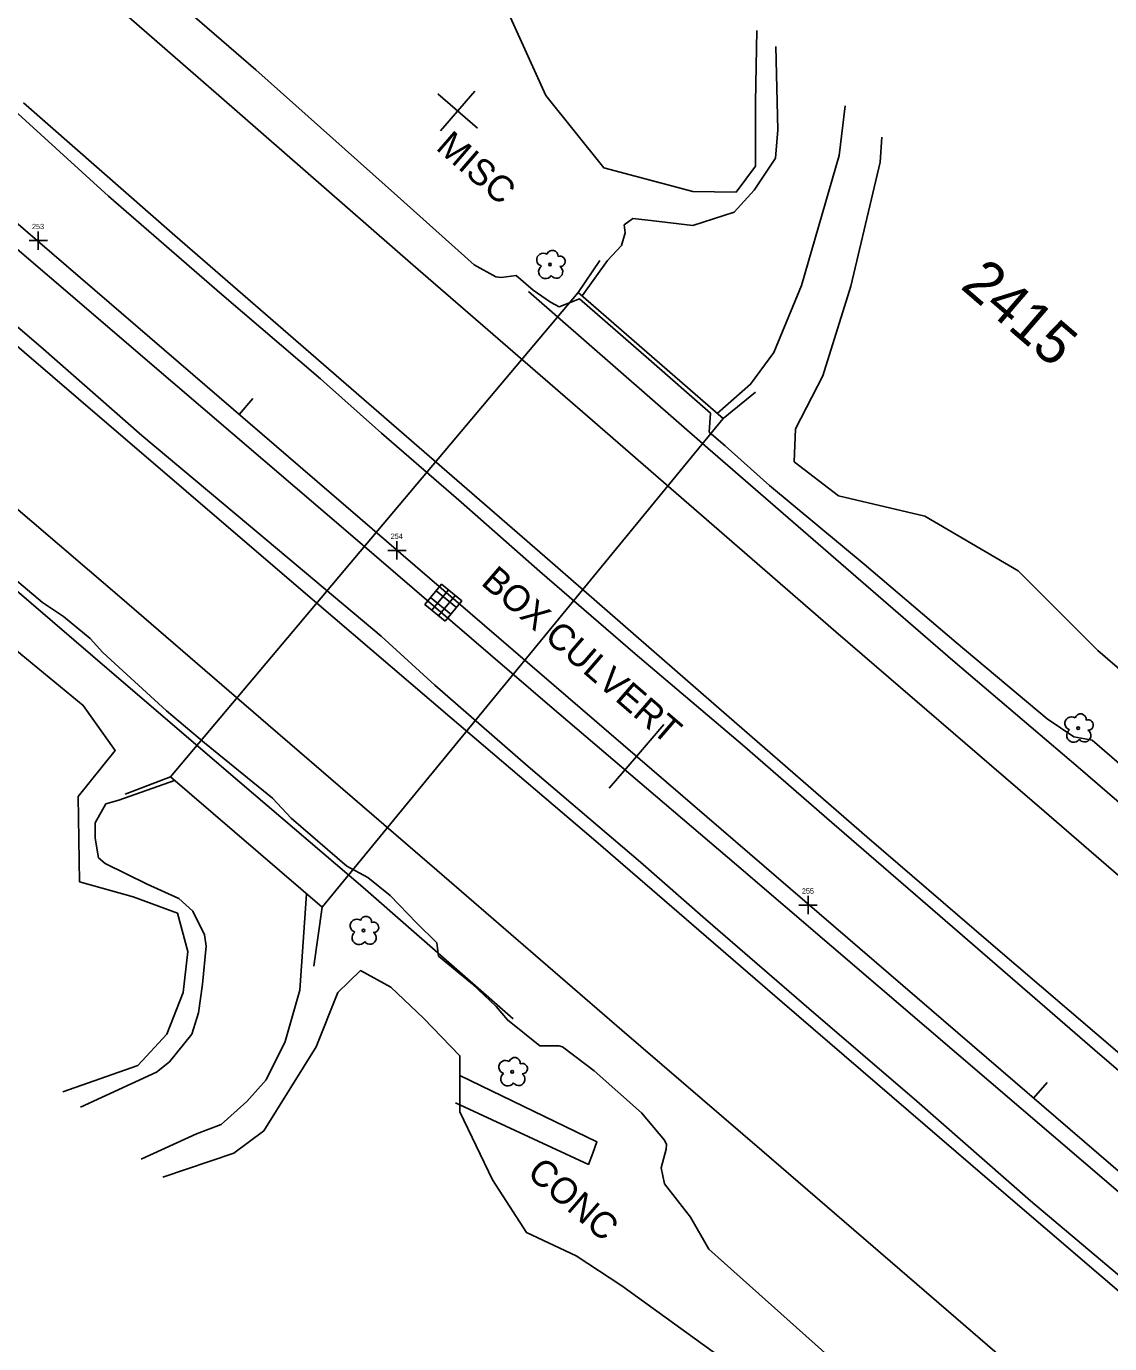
# Model space of a CAD drawing. Extents: x 2076109 to 2080761, y 592812 to 596750.
# Drawn here: x 2079627.6 to 2079834.4, y 593575.6 to 593826.9 of the extents above; entities that cross this region are included whole.
import ezdxf

# ---------------------------------------------------------------- set-up
doc = ezdxf.new("R2010")
doc.units = 0
for name, color, linetype in [('Default', 7, 'Continuous'), ('RD_EX_Bridge', 7, 'Continuous'), ('RD_EX_Bridge_txCode', 7, 'Continuous'), ('RD_EX_Conc', 7, 'Continuous'), ('RD_EX_Conc_txCode', 7, 'Continuous'), ('RD_EX_DR_Inlet', 7, 'Continuous'), ('RD_EX_DR_Pipe', 7, 'Continuous'), ('RD_EX_GuardRail', 7, 'Continuous'), ('RD_EX_H2O', 7, 'Continuous'), ('RD_EX_Misc', 7, 'Continuous'), ('RD_EX_Misc_txCode', 7, 'Continuous'), ('RD_EX_Road', 7, 'Continuous'), ('RD_EX_VEG', 7, 'Continuous'), ('RD_HC_Cl', 7, 'Continuous'), ('RD_HC_Data_Tic', 7, 'Continuous'), ('RD_HC_TX_Sta50', 7, 'Continuous')]:
    doc.layers.add(name, color=color, linetype=linetype)

msp = doc.modelspace()

# ---------------------------------------------------------------- linework, layer by layer
at = {"layer": 'Default'}
for p, q in [((2079631.63, 593786.02), (2079628.13, 593786.02)), ((2079631.63, 593786.02), (2079628.13, 593786.02)), ((2079629.88, 593787.77), (2079629.88, 593784.27)), ((2079629.88, 593787.77), (2079629.88, 593784.27)), ((2079698.34, 593728.68), (2079698.34, 593725.18)), ((2079698.34, 593728.68), (2079698.34, 593725.18)), ((2079700.09, 593726.93), (2079696.59, 593726.93)), ((2079700.09, 593726.93), (2079696.59, 593726.93)), ((2079776.81, 593661), (2079776.81, 593657.5)), ((2079776.81, 593661), (2079776.81, 593657.5)), ((2079778.56, 593659.25), (2079775.06, 593659.25)), ((2079778.56, 593659.25), (2079775.06, 593659.25))]:
    msp.add_line(p, q, dxfattribs=at)
at = {"layer": 'RD_EX_Bridge'}
for p, q in [((2079655.12, 593683.72), (2079646.47, 593680.41)), ((2079655.12, 593683.72), (2079646.47, 593680.41)), ((2079655.12, 593683.72), (2079684.06, 593658.88)), ((2079655.12, 593683.72), (2079684.06, 593658.88)), ((2079682.49, 593647.64), (2079684.06, 593658.88)), ((2079682.49, 593647.64), (2079684.06, 593658.88))]:
    msp.add_line(p, q, dxfattribs=at)
msp.add_lwpolyline([(2079737.04, 593782.21), (2079732.93, 593776.12), (2079760.58, 593752.07), (2079766.75, 593757.09)], dxfattribs=at)
msp.add_lwpolyline([(2079737.04, 593782.21), (2079732.93, 593776.12), (2079760.58, 593752.07), (2079766.75, 593757.09)], dxfattribs=at)
at = {"layer": 'RD_EX_Conc'}
msp.add_lwpolyline([(2079710.35, 593626.77), (2079736.52, 593614.13), (2079735.75, 593611.96), (2079734.89, 593609.79), (2079709.53, 593621.55)], dxfattribs=at)
msp.add_lwpolyline([(2079710.35, 593626.77), (2079736.52, 593614.13), (2079735.75, 593611.96), (2079734.89, 593609.79), (2079709.53, 593621.55)], dxfattribs=at)
at = {"layer": 'RD_EX_DR_Inlet'}
for p, q in [((2079704.75, 593717.93), (2079708.61, 593714.75)), ((2079704.75, 593717.93), (2079708.61, 593714.75)), ((2079704.98, 593715.54), (2079708.16, 593719.4)), ((2079704.98, 593715.54), (2079708.16, 593719.4)), ((2079705.83, 593719.24), (2079709.69, 593716.06)), ((2079705.83, 593719.24), (2079709.69, 593716.06)), ((2079706.29, 593714.46), (2079709.47, 593718.32)), ((2079706.29, 593714.46), (2079709.47, 593718.32))]:
    msp.add_line(p, q, dxfattribs=at)
msp.add_lwpolyline([(2079707.52, 593713.44), (2079703.67, 593716.62), (2079706.85, 593720.48), (2079710.71, 593717.3)], close=True, dxfattribs=at)
msp.add_lwpolyline([(2079707.52, 593713.44), (2079703.67, 593716.62), (2079706.85, 593720.48), (2079710.71, 593717.3)], close=True, dxfattribs=at)
at = {"layer": 'RD_EX_DR_Pipe'}
for p, q in [((2079655.12, 593683.72), (2079732.93, 593776.12)), ((2079655.12, 593683.72), (2079732.93, 593776.12)), ((2079760.58, 593752.07), (2079684.06, 593658.88)), ((2079760.58, 593752.07), (2079684.06, 593658.88))]:
    msp.add_line(p, q, dxfattribs=at)
at = {"layer": 'RD_EX_GuardRail'}
for points in [[(2080184.35, 593305.04), (2080148.2, 593335.86), (2080111.67, 593367.26), (2080075.44, 593398.3), (2080039.84, 593429.28), (2080003.46, 593460.74), (2079967.36, 593491.67), (2079919.17, 593532.83), (2079871.19, 593574.23), (2079835.53, 593605.02), (2079799.41, 593635.93), (2079763.16, 593666.95), (2079727.5, 593697.27), (2079690.37, 593729.2), (2079655.55, 593758.99), (2079608.01, 593799.67)], [(2079551.16, 593782.51), (2079573.31, 593764.15), (2079609.03, 593733.58), (2079644.36, 593703.26), (2079668.38, 593682.73), (2079691.86, 593662.7), (2079720.53, 593637.58)], [(2079551.16, 593782.51), (2079573.31, 593764.15), (2079609.03, 593733.58), (2079644.36, 593703.26), (2079668.38, 593682.73), (2079691.86, 593662.7), (2079720.53, 593637.58)], [(2079915.69, 593611.77), (2079890.2, 593632.66), (2079880.48, 593640.55), (2079865.92, 593652.95), (2079847.21, 593669.28), (2079828.34, 593685.59), (2079804.41, 593705.91), (2079785.94, 593721.98), (2079757.68, 593746.46), (2079723.46, 593776.29)], [(2079915.69, 593611.77), (2079890.2, 593632.66), (2079880.48, 593640.55), (2079865.92, 593652.95), (2079847.21, 593669.28), (2079828.34, 593685.59), (2079804.41, 593705.91), (2079785.94, 593721.98), (2079757.68, 593746.46), (2079723.46, 593776.29)]]:
    msp.add_lwpolyline(points, dxfattribs=at)
at = {"layer": 'RD_EX_H2O'}
for points in [[(2079733.67, 593775.48), (2079738.53, 593782.22), (2079741.21, 593785.08), (2079741.87, 593787.48), (2079741.71, 593789.01), (2079743.36, 593790.27), (2079746.82, 593789.88), (2079754.78, 593788.92), (2079762.7, 593791.43), (2079766.52, 593795.63), (2079770.59, 593801.74), (2079771.04, 593807.18), (2079770.62, 593823.03)], [(2079733.67, 593775.48), (2079738.53, 593782.22), (2079741.21, 593785.08), (2079741.87, 593787.48), (2079741.71, 593789.01), (2079743.36, 593790.27), (2079746.82, 593789.88), (2079754.78, 593788.92), (2079762.7, 593791.43), (2079766.52, 593795.63), (2079770.59, 593801.74), (2079771.04, 593807.18), (2079770.62, 593823.03)], [(2079783.85, 593811.74), (2079782.72, 593802.27), (2079775.53, 593777.46), (2079770.25, 593764.71), (2079765.82, 593758.62), (2079759.45, 593753.06)], [(2079783.85, 593811.74), (2079782.72, 593802.27), (2079775.53, 593777.46), (2079770.25, 593764.71), (2079765.82, 593758.62), (2079759.45, 593753.06)], [(2079637.95, 593620.74), (2079652.43, 593627.36), (2079654.92, 593629.38), (2079659.21, 593634.65), (2079660.48, 593638.73), (2079661.25, 593644.19), (2079661.96, 593651.45), (2079661.61, 593653.61), (2079659.39, 593658.11), (2079656.73, 593660.5), (2079650.67, 593663.24), (2079642.69, 593667.18), (2079641.42, 593668.28), (2079640.75, 593672.01), (2079640.78, 593674.94), (2079642.81, 593678.57), (2079645.29, 593679.29), (2079655.89, 593683.06)], [(2079637.95, 593620.74), (2079652.43, 593627.36), (2079654.92, 593629.38), (2079659.21, 593634.65), (2079660.48, 593638.73), (2079661.25, 593644.19), (2079661.96, 593651.45), (2079661.61, 593653.61), (2079659.39, 593658.11), (2079656.73, 593660.5), (2079650.67, 593663.24), (2079642.69, 593667.18), (2079641.42, 593668.28), (2079640.75, 593672.01), (2079640.78, 593674.94), (2079642.81, 593678.57), (2079645.29, 593679.29), (2079655.89, 593683.06)], [(2079681.07, 593661.44), (2079679.81, 593643.05), (2079677.04, 593633.22), (2079673.4, 593625.9), (2079669.68, 593621.8), (2079664.78, 593617.43), (2079660.09, 593615.64), (2079649.66, 593610.86), (2079649.56, 593610.83)], [(2079681.07, 593661.44), (2079679.81, 593643.05), (2079677.04, 593633.22), (2079673.4, 593625.9), (2079669.68, 593621.8), (2079664.78, 593617.43), (2079660.09, 593615.64), (2079649.66, 593610.86), (2079649.56, 593610.83)]]:
    msp.add_lwpolyline(points, dxfattribs=at)
at = {"layer": 'RD_EX_Misc'}
for p, q in [((2079706.13, 593814.01), (2079713.69, 593807.47)), ((2079706.13, 593814.01), (2079713.69, 593807.47)), ((2079706.64, 593806.96), (2079713.18, 593814.53)), ((2079706.64, 593806.96), (2079713.18, 593814.53))]:
    msp.add_line(p, q, dxfattribs=at)
for points in [[(2080217.04, 593337.18), (2080172.52, 593375.33), (2080138.87, 593404.33), (2080108.48, 593430.29), (2080078.14, 593456.52), (2080038.92, 593490.11), (2080009.05, 593515.98), (2079977.29, 593543.26), (2079946.15, 593570.28), (2079919.11, 593593.43), (2079890.41, 593617.97), (2079858.75, 593645.26), (2079821.86, 593677.15), (2079782.12, 593711.42), (2079735.64, 593751.71), (2079701.45, 593781.37), (2079664.35, 593813.72), (2079643.76, 593831.64)], [(2079627.11, 593812.28), (2079655.96, 593786.97), (2079692.98, 593754.86), (2079726.56, 593725.77), (2079758.83, 593697.63), (2079788.04, 593672.28), (2079811.24, 593652.3), (2079842, 593625.98), (2079868.07, 593603.53), (2079898.03, 593577.49), (2079923.97, 593555.11), (2079945.84, 593536.38), (2079972.92, 593513.01), (2079994.98, 593494.07), (2080016.85, 593475.02), (2080049.11, 593447.31), (2080079.81, 593420.95), (2080112.25, 593393.22), (2080144.25, 593365.64), (2080177.02, 593337.45), (2080203.16, 593314.91)], [(2080178.72, 593290.98), (2080145.52, 593319.67), (2080116.25, 593344.84), (2080082.12, 593374.03), (2080051.53, 593400.34), (2080021.2, 593426.66), (2079989.82, 593453.61), (2079954.27, 593484.21), (2079917.77, 593515.59), (2079872.88, 593554.03), (2079843.75, 593579.04), (2079811.01, 593607.11), (2079771.89, 593640.76), (2079736.28, 593671.46), (2079708.41, 593695.19), (2079678.65, 593720.6), (2079637.6, 593755.82), (2079606.82, 593782.2)], [(2079590.1, 593765.16), (2079617.13, 593742.26), (2079645.39, 593718.11), (2079673.76, 593693.67), (2079705.98, 593665.94), (2079741.28, 593635.42), (2079768.01, 593612.45), (2079794.32, 593589.74), (2079821.72, 593566.1), (2079850.25, 593541.52), (2079880.79, 593515.25), (2079909.32, 593490.67), (2079940.4, 593463.94), (2079966.11, 593441.94), (2079995.57, 593416.65), (2080039.13, 593379.08), (2080076.01, 593347.24), (2080106.97, 593320.7), (2080137.83, 593294.2), (2080162.8, 593272.51)]]:
    msp.add_lwpolyline(points, dxfattribs=at)
at = {"layer": 'RD_EX_Road'}
for points in [[(2079642.44, 593843.74), (2079671.4, 593818.61), (2079698.44, 593794.49), (2079713.05, 593781.4), (2079717.21, 593779.09), (2079718.21, 593779.01), (2079721.07, 593779.37), (2079724.35, 593776.58), (2079727.62, 593774.31), (2079729.3, 593773.41), (2079733.2, 593774.9), (2079746.42, 593763.41), (2079758.17, 593753.11), (2079757.95, 593749.51), (2079761, 593746.87), (2079769.45, 593739.29), (2079787.52, 593724.31), (2079805.07, 593709.37), (2079822.43, 593694.78), (2079827.54, 593691.38), (2079831.04, 593690.71), (2079845.61, 593678.16)], [(2079915.58, 593559.4), (2079891.77, 593580.17), (2079865.9, 593602.21), (2079832.47, 593630.76), (2079804.37, 593655.14), (2079781.34, 593675), (2079764.28, 593689.81), (2079743.82, 593707.18), (2079725.61, 593722.92), (2079710.62, 593736.11), (2079695.41, 593749.27), (2079683.78, 593759.65), (2079664.93, 593775.72), (2079643.32, 593794.49), (2079625.35, 593810.82)], [(2079603.88, 593788.4), (2079630.41, 593765.74), (2079649.64, 593748.83), (2079670, 593731.78), (2079695.31, 593710.54), (2079705.57, 593701.2), (2079723.39, 593685.71), (2079744.81, 593667.42), (2079757.22, 593656.6), (2079776.93, 593639.55), (2079797.54, 593621.87), (2079819.28, 593602.83), (2079847.19, 593579.3), (2079876.99, 593553.77)], [(2079810.39, 593546.7), (2079757.88, 593593.63), (2079754.34, 593599.71), (2079749.43, 593606.09), (2079748.79, 593609.14), (2079749.7, 593612.71), (2079749.78, 593613.61), (2079749.42, 593614.43), (2079744.99, 593619.65), (2079735.99, 593627.66), (2079729.93, 593632.21), (2079729.24, 593632.44), (2079725.59, 593632.4), (2079719.42, 593637.36), (2079717.3, 593639.89), (2079712.71, 593644.23), (2079706.29, 593649.55), (2079705.96, 593652.06), (2079702.06, 593655.9), (2079697.06, 593661.1), (2079692.81, 593664.54), (2079688.8, 593666.71), (2079678.15, 593675.87), (2079674.6, 593679.68), (2079661.62, 593690.22), (2079654.37, 593696.3), (2079642.19, 593707.43), (2079639.81, 593710.09), (2079634.69, 593714.29), (2079630.72, 593716.98), (2079618.37, 593727.34)]]:
    msp.add_lwpolyline(points, dxfattribs=at)
at = {"layer": 'RD_EX_VEG'}
for points in [[(2079767.02, 593826.09), (2079766.8, 593812.46), (2079766.79, 593800.24), (2079763.08, 593795.3), (2079754.82, 593795.4), (2079737.81, 593799.93), (2079726.77, 593813.73), (2079719.92, 593828.73), (2079693.15, 593840.4), (2079683.55, 593839.8), (2079654.76, 593860.06)], [(2079767.02, 593826.09), (2079766.8, 593812.46), (2079766.79, 593800.24), (2079763.08, 593795.3), (2079754.82, 593795.4), (2079737.81, 593799.93), (2079726.77, 593813.73), (2079719.92, 593828.73), (2079693.15, 593840.4), (2079683.55, 593839.8), (2079654.76, 593860.06)], [(2079968.58, 593624.66), (2079958.38, 593631.05), (2079939.2, 593650.42), (2079923.3, 593657.31), (2079908.32, 593663.78), (2079895.34, 593672.97), (2079889.9, 593684.89), (2079877.81, 593696.83), (2079858.95, 593693.87), (2079841.76, 593699.48), (2079832.11, 593707.82), (2079816.9, 593723.01), (2079799.06, 593733.44), (2079782.58, 593737.31), (2079774.16, 593743.85), (2079774.4, 593750.13), (2079779.63, 593760.24), (2079784.95, 593777.32), (2079790.58, 593800.97), (2079790.86, 593805.75)], [(2079968.58, 593624.66), (2079958.38, 593631.05), (2079939.2, 593650.42), (2079923.3, 593657.31), (2079908.32, 593663.78), (2079895.34, 593672.97), (2079889.9, 593684.89), (2079877.81, 593696.83), (2079858.95, 593693.87), (2079841.76, 593699.48), (2079832.11, 593707.82), (2079816.9, 593723.01), (2079799.06, 593733.44), (2079782.58, 593737.31), (2079774.16, 593743.85), (2079774.4, 593750.13), (2079779.63, 593760.24), (2079784.95, 593777.32), (2079790.58, 593800.97), (2079790.86, 593805.75)], [(2079558.82, 593758.54), (2079567.11, 593752.59), (2079592, 593738.1), (2079599.15, 593721.73), (2079608.32, 593715.84), (2079616.47, 593715.83), (2079626.54, 593707.13), (2079638.47, 593697.36), (2079644.56, 593688.76), (2079637.54, 593679.97), (2079637.77, 593663.73), (2079648.02, 593660.83), (2079656.44, 593657.74), (2079658.47, 593650.41), (2079657.58, 593642.57), (2079654.43, 593634.64), (2079648.92, 593628.68), (2079634.56, 593623.62)], [(2079558.82, 593758.54), (2079567.11, 593752.59), (2079592, 593738.1), (2079599.15, 593721.73), (2079608.32, 593715.84), (2079616.47, 593715.83), (2079626.54, 593707.13), (2079638.47, 593697.36), (2079644.56, 593688.76), (2079637.54, 593679.97), (2079637.77, 593663.73), (2079648.02, 593660.83), (2079656.44, 593657.74), (2079658.47, 593650.41), (2079657.58, 593642.57), (2079654.43, 593634.64), (2079648.92, 593628.68), (2079634.56, 593623.62)], [(2079653.66, 593607.33), (2079667.22, 593611.93), (2079672.97, 593616.22), (2079682.93, 593632.24), (2079687.05, 593642.57), (2079691.42, 593646.76), (2079697.21, 593643.61), (2079703.4, 593637.7), (2079710.35, 593630.53), (2079710.36, 593619.82), (2079716.56, 593606.86), (2079723.06, 593596.8), (2079732.52, 593592.32), (2079741.28, 593586.6), (2079759.63, 593573.33)]]:
    msp.add_lwpolyline(points, dxfattribs=at)
for centre in [(2079727.55, 593781.47), (2079727.55, 593781.47), (2079828.35, 593693.02), (2079828.35, 593693.02), (2079691.97, 593654.41), (2079691.97, 593654.41), (2079720.35, 593627.46), (2079720.35, 593627.46)]:
    msp.add_circle(centre, 0.25, dxfattribs=at)
for centre, radius, start, end in [((2079726.27, 593782.38), 1.26, 55.6193, 253.9015), ((2079726.27, 593782.38), 1.26, 55.6193, 253.9015), ((2079728.02, 593783.11), 1.08, 354.1438, 163.9235), ((2079728.02, 593783.11), 1.08, 354.1438, 163.9235), ((2079729.46, 593782.08), 0.995, 267.9301, 111.2143), ((2079729.46, 593782.08), 0.995, 267.9301, 111.2143), ((2079726.7, 593780.1), 1.32, 126.0502, 324.9265), ((2079726.7, 593780.1), 1.32, 126.0502, 324.9265), ((2079728.76, 593780.06), 1.22, 215.7342, 57.2722), ((2079728.76, 593780.06), 1.22, 215.7342, 57.2722), ((2079827.06, 593693.92), 1.26, 55.6193, 253.9015), ((2079827.06, 593693.92), 1.26, 55.6193, 253.9015), ((2079828.81, 593694.66), 1.08, 354.1438, 163.9235), ((2079828.81, 593694.66), 1.08, 354.1438, 163.9235), ((2079827.49, 593691.65), 1.32, 126.0502, 324.9265), ((2079827.49, 593691.65), 1.32, 126.0502, 324.9265), ((2079829.56, 593691.6), 1.22, 215.7342, 57.2722), ((2079829.56, 593691.6), 1.22, 215.7342, 57.2722), ((2079830.25, 593693.62), 0.995, 267.9301, 111.2143), ((2079830.25, 593693.62), 0.995, 267.9301, 111.2143), ((2079692.43, 593656.05), 1.08, 354.1438, 163.9235), ((2079692.43, 593656.05), 1.08, 354.1438, 163.9235), ((2079690.68, 593655.32), 1.26, 55.6193, 253.9015), ((2079690.68, 593655.32), 1.26, 55.6193, 253.9015), ((2079693.87, 593655.01), 0.995, 267.9301, 111.2143), ((2079693.87, 593655.01), 0.995, 267.9301, 111.2143), ((2079691.11, 593653.04), 1.32, 126.0502, 324.9265), ((2079691.11, 593653.04), 1.32, 126.0502, 324.9265), ((2079693.18, 593653), 1.22, 215.7342, 57.2722), ((2079693.18, 593653), 1.22, 215.7342, 57.2722), ((2079719.06, 593628.37), 1.26, 55.6193, 253.9015), ((2079719.06, 593628.37), 1.26, 55.6193, 253.9015), ((2079720.81, 593629.1), 1.08, 354.1438, 163.9235), ((2079720.81, 593629.1), 1.08, 354.1438, 163.9235), ((2079719.49, 593626.09), 1.32, 126.0502, 324.9265), ((2079719.49, 593626.09), 1.32, 126.0502, 324.9265), ((2079721.56, 593626.05), 1.22, 215.7342, 57.2722), ((2079721.56, 593626.05), 1.22, 215.7342, 57.2722), ((2079722.25, 593628.07), 0.995, 267.9301, 111.2143), ((2079722.25, 593628.07), 0.995, 267.9301, 111.2143)]:
    msp.add_arc(centre, radius, start, end, dxfattribs=at)
at = {"layer": 'RD_HC_Cl'}
msp.add_line((2079511.94, 593887.33), (2080761.16, 592812.48), dxfattribs=at)
at = {"layer": 'RD_HC_Data_Tic'}
for p, q in [((2079668.25, 593752.84), (2079670.86, 593755.88)), ((2079668.25, 593752.84), (2079670.86, 593755.88)), ((2079744.05, 593687.62), (2079749.27, 593693.69)), ((2079744.05, 593687.62), (2079749.27, 593693.69)), ((2079744.05, 593687.62), (2079738.83, 593681.56)), ((2079744.05, 593687.62), (2079738.83, 593681.56)), ((2079819.85, 593622.4), (2079822.46, 593625.43)), ((2079819.85, 593622.4), (2079822.46, 593625.43))]:
    msp.add_line(p, q, dxfattribs=at)

# ---------------------------------------------------------------- texts
at = {"layer": 'Default'}
for s, p in [('253', (2079628.7, 593788.22)), ('253', (2079628.7, 593788.22)), ('254', (2079697.16, 593729.13)), ('254', (2079697.16, 593729.13)), ('255', (2079775.62, 593661.45)), ('255', (2079775.62, 593661.45))]:
    msp.add_text(s, height=1, dxfattribs=at).set_placement(p)
at = {"layer": 'RD_EX_Bridge_txCode'}
msp.add_text('BOX CULVERT', height=5, rotation=319.1675, dxfattribs=at).set_placement((2079714.18, 593720.54))
msp.add_text('BOX CULVERT', height=5, rotation=319.1675, dxfattribs=at).set_placement((2079714.18, 593720.54))
at = {"layer": 'RD_EX_Conc_txCode'}
msp.add_text('CONC', height=5, rotation=319.1675, dxfattribs=at).set_placement((2079722.95, 593607.76))
msp.add_text('CONC', height=5, rotation=319.1675, dxfattribs=at).set_placement((2079722.95, 593607.76))
at = {"layer": 'RD_EX_Misc_txCode'}
msp.add_text(' MISC', height=5, rotation=319.1496, dxfattribs=at).set_placement((2079704.17, 593804.75))
msp.add_text(' MISC', height=5, rotation=319.1496, dxfattribs=at).set_placement((2079704.17, 593804.75))
at = {"layer": 'RD_HC_TX_Sta50'}
msp.add_text('2415', height=8, rotation=319.2904, dxfattribs=at).set_placement((2079805.67, 593777.08))
msp.add_text('2415', height=8, rotation=319.2904, dxfattribs=at).set_placement((2079805.67, 593777.08))

doc.saveas('drawing.dxf')
